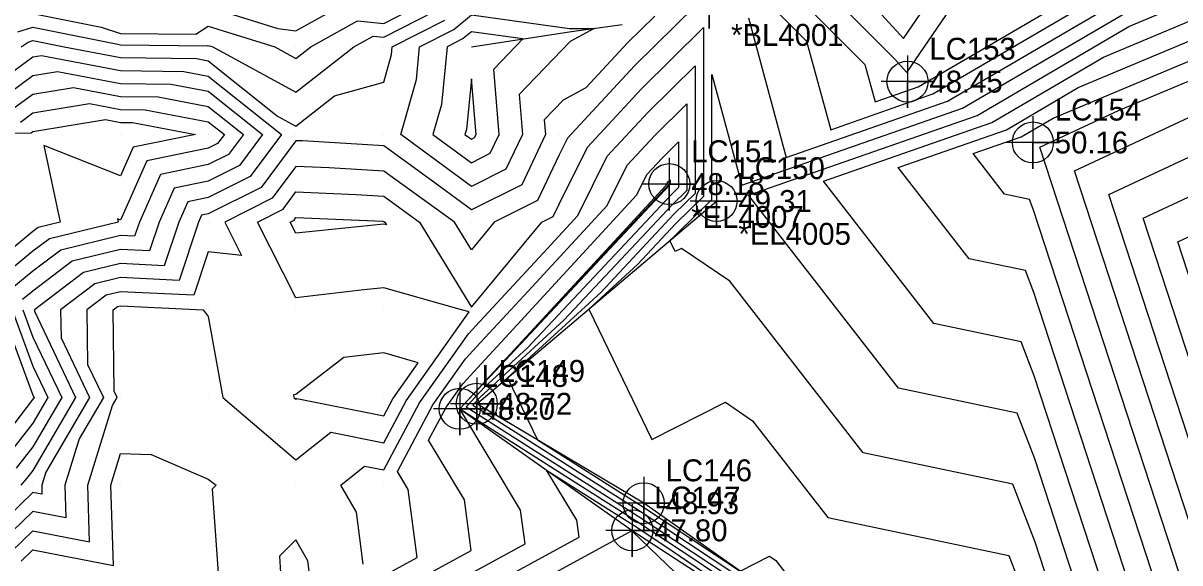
# Model space of a CAD drawing. Extents: x 2188792 to 2191981, y 386090 to 389710.
# Drawn here: x 2189959 to 2190090.9, y 387701.3 to 387762.9 of the extents above; entities that cross this region are included whole.
import ezdxf

# ---------------------------------------------------------------- set-up
doc = ezdxf.new("R2010")
doc.units = 0
for name, color, linetype in [('DTM Contours Major', 7, 'Continuous'), ('DTM Contours Minor', 7, 'Continuous'), ('Exist DTM Breakline', 7, 'Continuous'), ('Exist DTM Breakline Cogo Comment', 7, 'Continuous'), ('Exist DTM Breakline Cogo Elevation', 7, 'Continuous'), ('Exist DTM Breakline Cogo Number', 7, 'Continuous'), ('Exist DTM Breakline Cogo Point CELL', 7, 'Continuous'), ('Exist DTM Breakline Underwater', 7, 'Continuous'), ('Exist DTM Breakline Underwater Cogo Comment', 7, 'Continuous'), ('Exist DTM Breakline Underwater Cogo Elevation', 7, 'Continuous'), ('Exist DTM Breakline Underwater Cogo Number', 7, 'Continuous'), ('Exist DTM Breakline Underwater Cogo Point CELL', 7, 'Continuous'), ('Exist DTM QL2 LIDAR Elevation Point', 7, 'Continuous'), ('Exist DTM Regular Point Underwater CELL', 7, 'Continuous'), ('Exist DTM Regular Point Underwater Cogo Comment', 7, 'Continuous'), ('Exist DTM Regular Point Underwater Cogo Elevation', 7, 'Continuous'), ('Exist DTM Regular Point Underwater Cogo Number', 7, 'Continuous'), ('PH Exist DTM Breakline', 7, 'Continuous')]:
    doc.layers.add(name, color=color, linetype=linetype)

msp = doc.modelspace()

# ---------------------------------------------------------------- linework, layer by layer
at = {"layer": 'DTM Contours Major'}
for points in [[(2190038.64, 387607.77), (2190040.51, 387613.08), (2190052.74, 387628.26), (2190051.83, 387637.48), (2190062.79, 387655.5), (2190066.78, 387661.14), (2190075.43, 387674.83), (2190075.4, 387676.25), (2190083.98, 387671.12), (2190090.42, 387692.01), (2190074.2, 387741.66), (2190073.77, 387742.76), (2190070.93, 387743.36), (2190067.33, 387747.99), (2190072.81, 387749.91), (2190076.45, 387752.04), (2190123.9, 387772)], [(2190041.7, 387763.49), (2190046.03, 387747.55), (2190064.43, 387753.98), (2190090.85, 387769.46)], [(2189960.1, 387763.96), (2189967.88, 387762.4), (2189970.1, 387761.7), (2189978.68, 387761.6), (2189980.11, 387762.53), (2189987.68, 387760.18), (2189990.11, 387758.85), (2189991.8, 387760.18), (2189997.14, 387763.15), (2190000.11, 387762.85), (2190004.97, 387765.32)], [(2189957.67, 387702.6), (2189960.1, 387704.96), (2189966.57, 387703.71), (2189966.36, 387710.17), (2189969.19, 387719.26), (2189969.73, 387720.17), (2189969.38, 387720.9), (2189969.25, 387730.17), (2189969.74, 387730.54), (2189970.1, 387730.63), (2189979.53, 387730.17), (2189980.11, 387729.39), (2189981.77, 387720.17), (2189990.11, 387713.03), (2189994.08, 387716.2), (2190000.11, 387714.99), (2190002.67, 387719.79), (2190009.86, 387729.92), (2190008.99, 387730.17), (2190000.11, 387732.68), (2189997.84, 387732.44), (2189990.11, 387731.52), (2189985.72, 387740.17), (2189988.64, 387741.64), (2189990.11, 387743.61), (2189996.96, 387743.32), (2190000.11, 387743.13), (2190004.2, 387740.17), (2190010.11, 387730.46), (2190018.14, 387740.17), (2190019.45, 387740.83), (2190020.11, 387742.22), (2190023.34, 387748.72), (2190029.48, 387755.35), (2190036.59, 387762.36), (2190036.58, 387743.11), (2190033.43, 387740.01), (2190029.05, 387735.34), (2190023.5, 387730.24), (2190030.68, 387715.36), (2190039.11, 387719.61), (2190042.19, 387717.51), (2190050.77, 387706.47), (2190071.4, 387702.13), (2190074.47, 387694.14)], [(2189957.45, 387752.83), (2189960.1, 387754.77), (2189964.74, 387755.54), (2189970.1, 387754.51), (2189974.38, 387754.45), (2189980.11, 387753.37), (2189984.11, 387750.18), (2189982.4, 387747.88), (2189980.11, 387746.73), (2189974.67, 387745.62), (2189972.25, 387740.17), (2189971.71, 387738.57), (2189970.1, 387738.64), (2189963.29, 387736.99), (2189960.1, 387734.58), (2189957.7, 387732.58)], [(2190010.47, 387749.81), (2190010.64, 387750.18), (2190010.11, 387756.53), (2190009.54, 387750.75), (2190009.37, 387750.18), (2190010.11, 387749.63), (2190010.47, 387749.81)], [(2190102.33, 387702.25), (2190090.68, 387737.92), (2190127.26, 387755.01)], [(2189957.74, 387730.17), (2189960.1, 387723.74), (2189961.81, 387720.17), (2189960.1, 387717.25), (2189957.02, 387713.26)], [(2189979.14, 387677.85), (2189984.68, 387683.75), (2189992.62, 387687.98), (2190022.39, 387704.24), (2190022.13, 387706.16), (2190018.69, 387711.88), (2190024.66, 387708.09), (2190028.69, 387705.54), (2190032.06, 387703.31), (2190053.47, 387688.73), (2190053.97, 387688.41), (2190055.02, 387687.68), (2190053.94, 387684.64), (2190054.75, 387651.06), (2190044.44, 387634.23), (2190026.28, 387610.83), (2190025.48, 387610.05), (2190010.8, 387591.13), (2189995.27, 387571.63), (2189973.27, 387580.1), (2189966.15, 387587.41), (2189944.82, 387593.84)], [(2189990.23, 387699.6), (2189991.63, 387700.36), (2189991.47, 387701.54), (2189990.11, 387703.93), (2189988.21, 387702.07), (2189988.34, 387700.17), (2189988.74, 387698.81), (2189990.23, 387699.6)]]:
    msp.add_lwpolyline(points, dxfattribs=at)
at = {"layer": 'DTM Contours Minor'}
for points in [[(2190052.75, 387768.42), (2190059.41, 387761.12), (2190083.03, 387795.7)], [(2190038.76, 387778.47), (2190058.35, 387758.79), (2190059.76, 387757.24), (2190085.55, 387794.99)], [(2190038.34, 387774.88), (2190054.99, 387758.15), (2190056.15, 387753.88), (2190061.08, 387755.6), (2190096.61, 387776.43)], [(2190015.59, 387594.34), (2190030.61, 387612.08), (2190034.89, 387617.6), (2190047.3, 387632.27), (2190050.28, 387636.51), (2190060.94, 387654.04), (2190069.28, 387665.82), (2190075.07, 387674.98), (2190075.02, 387677.21), (2190079.74, 387674.39), (2190083.28, 387685.87), (2190074.36, 387713.15), (2190072.35, 387718.38), (2190058.84, 387721.23), (2190041.72, 387743.25), (2190067.78, 387752.35), (2190085.09, 387762.49), (2190114.34, 387774.79)], [(2190014.01, 387592.03), (2190031.21, 387612.34), (2190033.44, 387615.22), (2190047.65, 387632.02), (2190049.27, 387634.32), (2190061.55, 387654.53), (2190068.45, 387664.26), (2190075.19, 387674.93), (2190075.15, 387676.89), (2190081.15, 387673.3), (2190085.66, 387687.92), (2190074.31, 387722.65), (2190072.82, 387726.51), (2190062.87, 387728.6), (2190050.26, 387744.83), (2190069.46, 387751.53), (2190082.21, 387759.01), (2190117.52, 387773.86)], [(2190015.34, 387593.15), (2190031.81, 387612.6), (2190032, 387612.85), (2190048.01, 387631.78), (2190048.26, 387632.13), (2190062.17, 387655.01), (2190067.61, 387662.7), (2190075.31, 387674.88), (2190075.28, 387676.57), (2190082.56, 387672.21), (2190088.04, 387689.97), (2190074.25, 387732.16), (2190073.3, 387734.64), (2190066.9, 387735.98), (2190058.79, 387746.41), (2190071.14, 387750.72), (2190079.33, 387755.52), (2190120.71, 387772.93)], [(2190037.93, 387771.29), (2190048.35, 387760.82), (2190051.09, 387750.72), (2190062.75, 387754.79), (2190093.73, 387772.95)], [(2190046.11, 387602.43), (2190050.04, 387613.57), (2190058.45, 387624.01), (2190056.43, 387644.51), (2190063.4, 387655.99), (2190065.94, 387659.58), (2190075.55, 387674.78), (2190075.53, 387675.94), (2190085.39, 387670.03), (2190092.8, 387694.06), (2190074.94, 387748.71), (2190083.92, 387752.91), (2190127.09, 387771.06)], [(2190053.57, 387597.09), (2190059.56, 387614.06), (2190064.15, 387619.77), (2190061.02, 387651.54), (2190064.02, 387656.47), (2190065.11, 387658.01), (2190075.67, 387674.73), (2190075.66, 387675.62), (2190086.81, 387668.95), (2190095.19, 387696.11), (2190078.88, 387746.01), (2190130.07, 387769.93)], [(2190035.7, 387764.88), (2190028.7, 387757.99), (2190021.06, 387749.75), (2190020.11, 387747.83), (2190017.66, 387742.63), (2190012.73, 387740.17), (2190010.11, 387737), (2190008.18, 387740.17), (2190000.11, 387745.99), (2189993.91, 387746.37), (2189990.11, 387746.53), (2189987.39, 387742.89), (2189981.98, 387740.17), (2189983.91, 387736.37), (2189980.11, 387736.79), (2189978.45, 387731.83), (2189970.1, 387732.23), (2189968.45, 387731.83), (2189966.26, 387730.17), (2189966.34, 387723.94), (2189968.14, 387720.17), (2189965.38, 387715.45), (2189963.74, 387710.17), (2189963.86, 387706.42), (2189960.1, 387707.14), (2189956.56, 387703.72)], [(2189980.11, 387764.72), (2189988.02, 387762.27), (2189990.11, 387761.98), (2189995.37, 387764.91)], [(2189984.53, 387532.74), (2189985.31, 387544.52), (2189983.47, 387548.8), (2189986.68, 387548.09), (2189986.91, 387548.12), (2189997.2, 387555.6), (2189997.78, 387556.13), (2189998.07, 387556.59), (2190001.81, 387564.06), (2190025.83, 387576.7), (2190028.7, 387578.21), (2190035.67, 387586.74), (2190061.03, 387591.74), (2190069.08, 387614.56), (2190069.86, 387615.53), (2190068.06, 387633.74), (2190066.2, 387657.23), (2190065.62, 387658.57), (2190075.79, 387674.68), (2190075.78, 387675.3), (2190088.22, 387667.86), (2190097.57, 387698.16), (2190082.81, 387743.31), (2190129.14, 387764.96)], [(2190080.89, 387683.82), (2190074.42, 387703.64), (2190071.88, 387710.26), (2190054.81, 387713.85), (2190039.57, 387733.45), (2190034.09, 387737.18), (2190033.37, 387736.82), (2190032.76, 387738.09), (2190033.24, 387738.52), (2190033.61, 387738.92), (2190037.53, 387742.77), (2190037.54, 387757.01), (2190040.97, 387744.39), (2190066.11, 387753.16), (2190087.97, 387765.98)], [(2190031.02, 387763.68), (2190027.92, 387760.63), (2190023.15, 387755.48), (2190020.58, 387754.07), (2190018.43, 387751.85), (2190018.57, 387750.18), (2190015.86, 387744.42), (2190010.11, 387741.56), (2190004.83, 387745.45), (2190000.11, 387748.86), (2189990.86, 387749.43), (2189990.11, 387749.46), (2189986.15, 387744.14), (2189980.11, 387741.11), (2189979.33, 387740.95), (2189978.99, 387740.17), (2189976.77, 387733.51), (2189970.1, 387733.84), (2189967.16, 387733.12), (2189963.26, 387730.17), (2189963.31, 387726.97), (2189966.56, 387720.17), (2189961.57, 387711.63), (2189961.11, 387710.17), (2189961.14, 387709.13), (2189960.1, 387709.33), (2189955.44, 387704.83)], [(2189958.38, 387761.9), (2189960.1, 387762.42), (2189969.8, 387760.48), (2189970.1, 387760.39), (2189980.01, 387760.27), (2189980.11, 387760.34), (2189980.62, 387760.18), (2189990.11, 387754.99), (2189996.72, 387760.18), (2189998.9, 387761.39), (2190000.11, 387761.27), (2190006.02, 387764.27)], [(2190021.31, 387762.26), (2190021.5, 387762.27), (2190024.13, 387762.27), (2190021.39, 387760.78), (2190015.55, 387754.74), (2190015.93, 387750.18), (2190014.06, 387746.22), (2190010.11, 387744.25), (2190002.07, 387750.18), (2190003.84, 387756.44), (2190004.21, 387760.18), (2190008.12, 387762.16), (2190010.11, 387763.83), (2190021.31, 387762.26)], [(2189958.76, 387760.18), (2189959.56, 387760.72), (2189960.1, 387760.89), (2189963.66, 387760.18), (2189970.1, 387758.94), (2189978.75, 387758.83), (2189980.11, 387758.57), (2189988.01, 387752.27), (2189990.11, 387751.12), (2189994.5, 387754.57), (2190000.11, 387756.13), (2190001, 387759.29), (2190001.09, 387760.18), (2190007.07, 387763.21)], [(2190010.11, 387761.89), (2190009.18, 387761.11), (2190007.34, 387760.18), (2190006.69, 387753.59), (2190005.72, 387750.18), (2190010.11, 387746.94), (2190012.27, 387748.02), (2190013.28, 387750.18), (2190012.66, 387757.62), (2190015.99, 387761.07), (2190010.11, 387761.89)], [(2190027.25, 387517.33), (2189992.67, 387537.32), (2189992.48, 387538.02), (2189991.94, 387551.2), (2189998.06, 387555.65), (2189998.2, 387555.78), (2189998.27, 387555.89), (2189999.16, 387557.66), (2190031.13, 387574.49), (2190032.74, 387575.34), (2190036.65, 387580.11), (2190068.49, 387586.4), (2190073.13, 387599.54), (2190075.58, 387611.58), (2190075.18, 387615.87), (2190075.84, 387624.97), (2190073.15, 387658.81), (2190070.21, 387665.6), (2190075.92, 387674.64), (2190075.91, 387674.98), (2190089.63, 387666.77), (2190099.95, 387700.2), (2190086.74, 387740.62), (2190128.2, 387759.98)], [(2189954.99, 387755.29), (2189960.1, 387759.03), (2189961.09, 387759.19), (2189970.1, 387757.46), (2189977.3, 387757.37), (2189980.11, 387756.84), (2189988.46, 387750.18), (2189984.9, 387745.38), (2189980.11, 387742.98), (2189977.78, 387742.5), (2189976.74, 387740.17), (2189975.08, 387735.2), (2189970.1, 387735.44), (2189965.87, 387734.41), (2189960.27, 387730.17), (2189960.27, 387730.01), (2189964.98, 387720.17), (2189960.1, 387711.84), (2189959.38, 387710.9), (2189958.71, 387710.17)], [(2189956.22, 387754.06), (2189960.1, 387756.9), (2189962.92, 387757.37), (2189970.1, 387755.98), (2189975.84, 387755.91), (2189980.11, 387755.1), (2189986.29, 387750.18), (2189983.65, 387746.63), (2189980.11, 387744.85), (2189976.22, 387744.06), (2189974.5, 387740.17), (2189973.4, 387736.88), (2189970.1, 387737.04), (2189964.58, 387735.7), (2189960.1, 387732.31), (2189958.93, 387731.34)], [(2189997.78, 387701.14), (2189997, 387707.06), (2189995.22, 387710.17), (2189997.94, 387712.34), (2190000.11, 387711.91), (2190004.2, 387719.56), (2190009.79, 387727.44), (2190010.62, 387728.34), (2190018.74, 387737.11), (2190022.24, 387740.91), (2190025.61, 387747.7), (2190030.26, 387752.71), (2190035.64, 387758.02), (2190035.63, 387743.45), (2190033.25, 387741.11), (2190024.86, 387732.15), (2190014.23, 387722.4), (2190017.65, 387715.32), (2190029.61, 387707.74), (2190040.76, 387700.35), (2190044.12, 387702.04), (2190044.82, 387701.57), (2190046.74, 387699.09)], [(2189958.69, 387751.59), (2189960.1, 387752.63), (2189966.57, 387753.71), (2189970.1, 387753.03), (2189972.92, 387752.99), (2189980.11, 387751.63), (2189981.94, 387750.18), (2189981.15, 387749.13), (2189980.11, 387748.6), (2189973.11, 387747.17), (2189970.1, 387740.4), (2189969.74, 387740.54), (2189969.81, 387740.17), (2189962, 387738.28), (2189960.1, 387736.84), (2189956.46, 387733.82)], [(2189991.18, 387694.95), (2190003.93, 387701.91), (2190002.91, 387709.66), (2190001.67, 387711.73), (2190005.73, 387719.33), (2190009.45, 387724.58), (2190011.15, 387726.42), (2190016.58, 387732.28), (2190025.6, 387742.07), (2190027.89, 387746.67), (2190031.04, 387750.07), (2190034.69, 387753.67), (2190034.68, 387743.79), (2190033.06, 387742.2), (2190020.67, 387728.97), (2190011.08, 387720.17), (2190010.27, 387719.3), (2190013.12, 387717.49), (2190029.38, 387707.19), (2190042.99, 387698.17)], [(2189950.1, 387750.2), (2189959.92, 387750.36), (2189960.1, 387750.5), (2189968.4, 387751.88), (2189970.1, 387751.55), (2189971.46, 387751.53), (2189978.64, 387750.18), (2189971.55, 387748.73), (2189970.1, 387745.46), (2189961.37, 387748.9), (2189963.22, 387740.17), (2189960.71, 387739.57), (2189960.1, 387739.11), (2189955.22, 387735.06)], [(2189991.66, 387692.63), (2190010.08, 387702.69), (2190009.32, 387708.49), (2190005.23, 387715.3), (2190007.26, 387719.1), (2190009.12, 387721.72), (2190011.69, 387724.51), (2190014.42, 387727.46), (2190028.96, 387743.23), (2190030.16, 387745.65), (2190031.82, 387747.44), (2190033.74, 387749.33), (2190033.73, 387744.13), (2190032.88, 387743.3), (2190016.48, 387725.79), (2190011.65, 387721.36), (2190009.52, 387719.08), (2190016.97, 387714.36), (2190029.15, 387706.64), (2190039.34, 387699.88)], [(2190032.32, 387744.39), (2190032.43, 387744.62), (2190032.6, 387744.8), (2190032.78, 387744.98), (2190032.78, 387744.47), (2190032.7, 387744.39), (2190012.29, 387722.61), (2190012.22, 387722.55), (2190009.21, 387719.33), (2190012.22, 387722.59), (2190012.26, 387722.63), (2190032.32, 387744.39)], [(2189990.11, 387738.9), (2189989.46, 387740.17), (2189989.89, 387740.39), (2189990.11, 387740.68), (2190000.01, 387740.27), (2190000.11, 387740.26), (2190000.23, 387740.17), (2190000.42, 387739.87), (2190000.11, 387739.95), (2189991.25, 387739.03), (2189990.11, 387738.9)], [(2189956.52, 387730.17), (2189960.1, 387720.43), (2189960.23, 387720.17), (2189960.1, 387719.96), (2189955.84, 387714.43)], [(2189958.95, 387730.17), (2189960.1, 387727.05), (2189963.39, 387720.17), (2189960.1, 387714.55), (2189958.2, 387712.08)], [(2190001.15, 387720.02), (2190004.06, 387724.12), (2190000.11, 387725.27), (2189995.56, 387724.72), (2189990.11, 387720.52), (2189989.82, 387720.46), (2189989.87, 387720.17), (2189990.11, 387719.97), (2189990.22, 387720.06), (2190000.11, 387718.07), (2190001.15, 387720.02)], [(2189983.35, 387685.62), (2189992.14, 387690.3), (2190016.23, 387703.46), (2190015.73, 387707.32), (2190008.8, 387718.85), (2190020.82, 387711.23), (2190028.92, 387706.09), (2190035.7, 387701.6), (2190051.35, 387690.95), (2190061.18, 387684.5), (2190069.82, 387678.52), (2190071.79, 387677.6), (2190074.07, 387675.65), (2190074.34, 387675.35), (2190074.34, 387675.27), (2190074.29, 387675.19), (2190057.24, 387651.13), (2190056.35, 387649.66), (2190045.16, 387633.75), (2190043.56, 387631.86), (2190026.99, 387610.5)], [(2189958.78, 387701.49), (2189960.1, 387702.77), (2189969.28, 387700.99), (2189968.99, 387710.17), (2189970.1, 387713.76), (2189973.59, 387713.66), (2189980.11, 387710.86), (2189981.02, 387710.17), (2189980.56, 387709.72), (2189981.23, 387700.17)], [(2190028.41, 387704.94), (2189993.1, 387685.66), (2189986.01, 387681.88), (2189981.07, 387676.62), (2189974.16, 387668.72), (2189963.51, 387636.08), (2189960.74, 387633.32), (2189946.06, 387642.63)], [(2189951.6, 387603.73), (2189965.7, 387599.48), (2189978.67, 387586.18), (2189994.77, 387579.98), (2190006.14, 387594.25), (2190016.89, 387608.1), (2190024.73, 387615.81), (2190040.84, 387636.57), (2190049.99, 387651.5), (2190049.18, 387684.99), (2190028.44, 387704.92), (2190028.41, 387704.94)]]:
    msp.add_lwpolyline(points, dxfattribs=at)
at = {"layer": 'Exist DTM Breakline'}
msp.add_lwpolyline([(2189920.87, 387592.29), (2189962.12, 387565.38), (2189980.08, 387549.91), (2189986.9, 387547.68), (2189998.33, 387555.67), (2190012.46, 387589.75), (2190048.08, 387631.73), (2190076.07, 387674.57), (2190074.56, 387678.38), (2190070.09, 387679.67), (2190029.77, 387708.1), (2190010.73, 387719.44), (2190038.07, 387742.58)], dxfattribs=at)
at = {"layer": 'Exist DTM Breakline Cogo Point CELL'}
for points in [[(2190038.07, 387745.58), (2190038.07, 387739.58), (2190038.07, 387742.58), (2190041.07, 387742.58), (2190035.07, 387742.58)], [(2190010.73, 387722.44), (2190010.73, 387716.44), (2190010.73, 387719.44), (2190013.73, 387719.44), (2190007.73, 387719.44)], [(2190029.77, 387711.1), (2190029.77, 387705.1), (2190029.77, 387708.1), (2190032.77, 387708.1), (2190026.77, 387708.1)]]:
    msp.add_lwpolyline(points, dxfattribs=at)
for centre in [(2190038.07, 387742.58), (2190010.73, 387719.44), (2190029.77, 387708.1)]:
    msp.add_circle(centre, 2.34, dxfattribs=at)
at = {"layer": 'Exist DTM Breakline Underwater'}
msp.add_lwpolyline([(2190032.68, 387744.51), (2190008.78, 387718.87), (2190028.46, 387705), (2190069.72, 387678.09), (2190072.89, 387677.33), (2190074.34, 387675.28), (2190044.85, 387633.97)], dxfattribs=at)
at = {"layer": 'Exist DTM Breakline Underwater Cogo Point CELL'}
for points in [[(2190032.68, 387747.51), (2190032.68, 387741.51), (2190032.68, 387744.51), (2190035.68, 387744.51), (2190029.68, 387744.51)], [(2190008.78, 387721.87), (2190008.78, 387715.87), (2190008.78, 387718.87), (2190011.78, 387718.87), (2190005.78, 387718.87)], [(2190028.46, 387708), (2190028.46, 387702), (2190028.46, 387705), (2190031.46, 387705), (2190025.46, 387705)]]:
    msp.add_lwpolyline(points, dxfattribs=at)
for centre in [(2190032.68, 387744.51), (2190008.78, 387718.87), (2190028.46, 387705)]:
    msp.add_circle(centre, 2.34, dxfattribs=at)
at = {"layer": 'Exist DTM QL2 LIDAR Elevation Point'}
for p, q in [((2189960.1, 387760.18), (2189960.1, 387760.18)), ((2189970.1, 387760.18), (2189970.1, 387760.18)), ((2189980.11, 387760.18), (2189980.11, 387760.18)), ((2189990.11, 387760.18), (2189990.11, 387760.18)), ((2190000.11, 387760.18), (2190000.11, 387760.18)), ((2189960.1, 387750.18), (2189960.1, 387750.18)), ((2189970.1, 387750.18), (2189970.1, 387750.18)), ((2189980.11, 387750.18), (2189980.11, 387750.18)), ((2189990.11, 387750.18), (2189990.11, 387750.18)), ((2190000.11, 387750.18), (2190000.11, 387750.18)), ((2190010.11, 387750.18), (2190010.11, 387750.18)), ((2190020.11, 387750.18), (2190020.11, 387750.18)), ((2189960.1, 387740.17), (2189960.1, 387740.17)), ((2189970.1, 387740.17), (2189970.1, 387740.17)), ((2189980.11, 387740.17), (2189980.11, 387740.17)), ((2189990.11, 387740.17), (2189990.11, 387740.17)), ((2190000.11, 387740.17), (2190000.11, 387740.17)), ((2190010.11, 387740.17), (2190010.11, 387740.17)), ((2190020.11, 387740.17), (2190020.11, 387740.17)), ((2189960.1, 387730.17), (2189960.1, 387730.17)), ((2189970.1, 387730.17), (2189970.1, 387730.17)), ((2189980.11, 387730.17), (2189980.11, 387730.17)), ((2189990.11, 387730.17), (2189990.11, 387730.17)), ((2190000.11, 387730.17), (2190000.11, 387730.17)), ((2190010.11, 387730.17), (2190010.11, 387730.17)), ((2189960.1, 387720.17), (2189960.1, 387720.17)), ((2189970.1, 387720.17), (2189970.1, 387720.17)), ((2189980.11, 387720.17), (2189980.11, 387720.17)), ((2189990.11, 387720.17), (2189990.11, 387720.17)), ((2190000.11, 387720.17), (2190000.11, 387720.17)), ((2189960.1, 387710.17), (2189960.1, 387710.17)), ((2189970.1, 387710.17), (2189970.1, 387710.17)), ((2189980.11, 387710.17), (2189980.11, 387710.17)), ((2189990.11, 387710.17), (2189990.11, 387710.17)), ((2190000.11, 387710.17), (2190000.11, 387710.17))]:
    msp.add_line(p, q, dxfattribs=at)
at = {"layer": 'Exist DTM Regular Point Underwater CELL'}
for points in [[(2190037.23, 387768.28), (2190037.23, 387762.28), (2190037.23, 387765.28), (2190040.23, 387765.28), (2190034.23, 387765.28)], [(2190059.85, 387759.2), (2190059.85, 387753.2), (2190059.85, 387756.2), (2190062.85, 387756.2), (2190056.85, 387756.2)], [(2190074.15, 387752.26), (2190074.15, 387746.26), (2190074.15, 387749.26), (2190077.15, 387749.26), (2190071.15, 387749.26)]]:
    msp.add_lwpolyline(points, dxfattribs=at)
for centre in [(2190059.85, 387756.2), (2190074.15, 387749.26)]:
    msp.add_circle(centre, 2.34, dxfattribs=at)
at = {"layer": 'PH Exist DTM Breakline'}
msp.add_lwpolyline([(2190010.11, 387760.18), (2190021.53, 387761.91), (2190027.3, 387762.72)], dxfattribs=at)

# ---------------------------------------------------------------- texts
at = {"layer": 'Exist DTM Breakline Cogo Comment'}
msp.add_text('*EL4005', height=2.5, dxfattribs=at).set_placement((2190040.57, 387737.58))
at = {"layer": 'Exist DTM Breakline Cogo Elevation'}
for s, p in [('49.31', (2190040.57, 387741.33)), ('48.72', (2190013.23, 387718.19)), ('48.93', (2190032.27, 387706.85))]:
    msp.add_text(s, height=2.5, dxfattribs=at).set_placement(p)
at = {"layer": 'Exist DTM Breakline Cogo Number'}
for s, p in [('LC150', (2190040.57, 387745.08)), ('LC149', (2190013.23, 387721.94)), ('LC146', (2190032.27, 387710.6))]:
    msp.add_text(s, height=2.5, dxfattribs=at).set_placement(p)
at = {"layer": 'Exist DTM Breakline Underwater Cogo Comment'}
msp.add_text('*EL4007', height=2.5, dxfattribs=at).set_placement((2190035.18, 387739.51))
at = {"layer": 'Exist DTM Breakline Underwater Cogo Elevation'}
for s, p in [('48.18', (2190035.18, 387743.26)), ('48.20', (2190011.28, 387717.62)), ('47.80', (2190030.96, 387703.75))]:
    msp.add_text(s, height=2.5, dxfattribs=at).set_placement(p)
at = {"layer": 'Exist DTM Breakline Underwater Cogo Number'}
for s, p in [('LC151', (2190035.18, 387747.01)), ('LC148', (2190011.28, 387721.37)), ('LC147', (2190030.96, 387707.5))]:
    msp.add_text(s, height=2.5, dxfattribs=at).set_placement(p)
at = {"layer": 'Exist DTM Regular Point Underwater Cogo Comment'}
msp.add_text('*BL4001', height=2.5, dxfattribs=at).set_placement((2190039.73, 387760.28))
at = {"layer": 'Exist DTM Regular Point Underwater Cogo Elevation'}
for s, p in [('48.45', (2190062.35, 387754.95)), ('50.16', (2190076.65, 387748.01))]:
    msp.add_text(s, height=2.5, dxfattribs=at).set_placement(p)
at = {"layer": 'Exist DTM Regular Point Underwater Cogo Number'}
for s, p in [('LC153', (2190062.35, 387758.7)), ('LC154', (2190076.65, 387751.76))]:
    msp.add_text(s, height=2.5, dxfattribs=at).set_placement(p)

doc.saveas('drawing.dxf')
